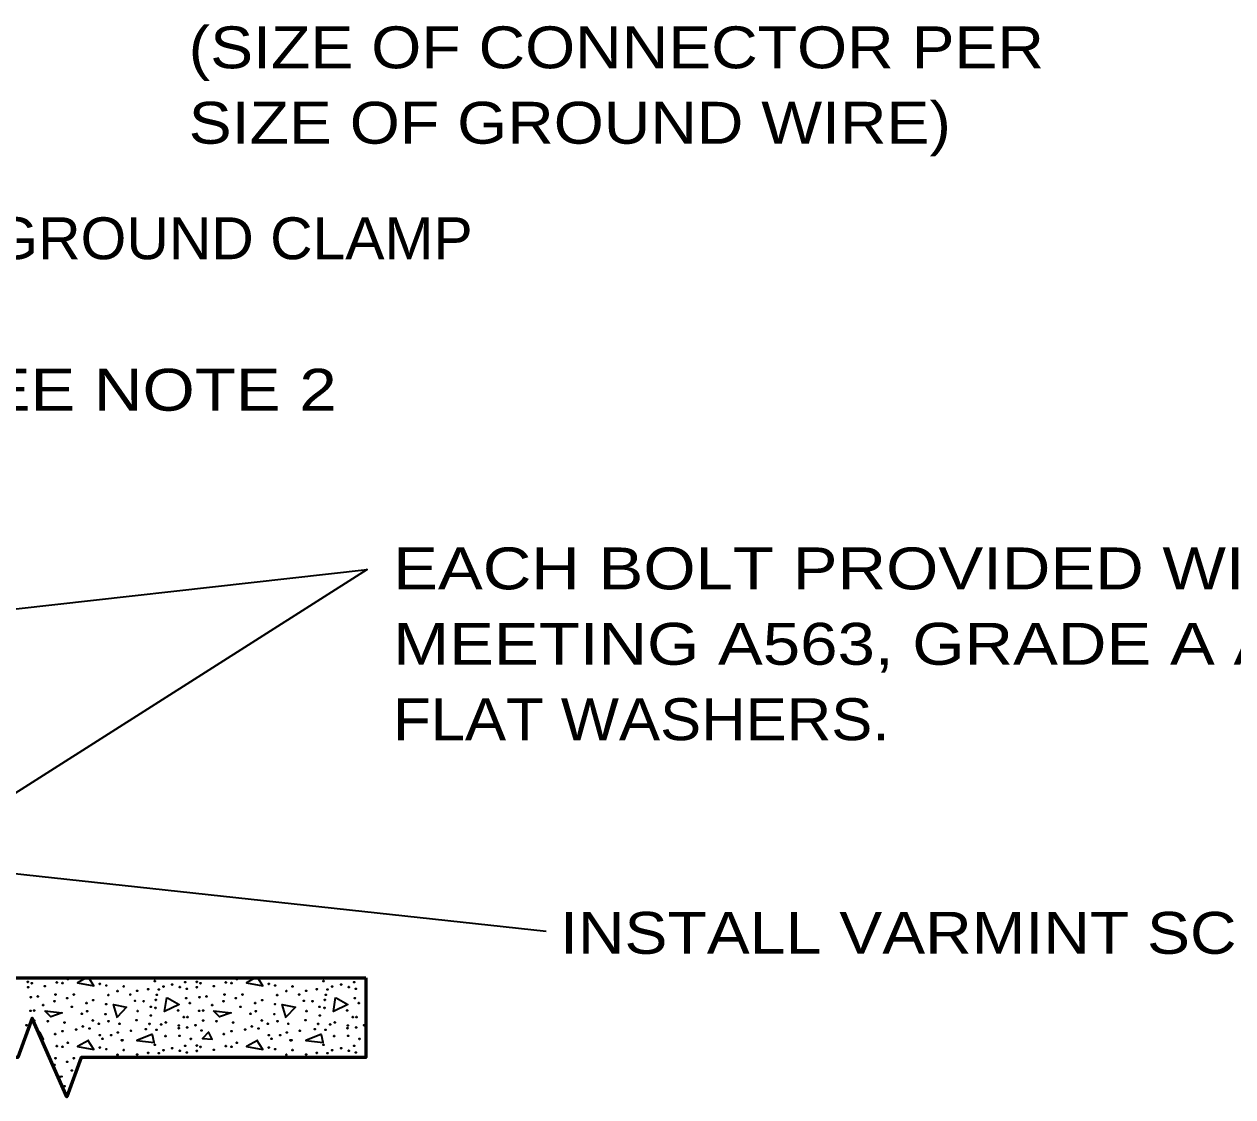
# Model space of a CAD drawing. Extents: x -1 to 679, y 0 to 440.
# Drawn here: x 464.1 to 536.2, y 233.6 to 297.7 of the extents above; entities that cross this region are included whole.
import ezdxf
from ezdxf.enums import TextEntityAlignment as Align

# ---------------------------------------------------------------- set-up
doc = ezdxf.new("R2010")
doc.units = 0
doc.layers.add('1', color=7, linetype='Continuous', lineweight=35)

msp = doc.modelspace()

# ---------------------------------------------------------------- linework, layer by layer
at = {"layer": '1'}
for p, q in [((460.988, 247.244), (495.251, 243.524)), ((465.041, 237.532), (464.96, 237.447))]:
    msp.add_line(p, q, dxfattribs=at)
at = {"layer": '1', "lineweight": 53}
msp.add_line((460.988, 240.744), (484.488, 240.744), dxfattribs=at)
at = {"layer": '1'}
for points in [[(458.988, 262.245), (484.563, 265.111), (458.988, 248.869)], [(467.818, 240.744), (467.281, 240.452), (468.261, 240.272), (467.957, 240.744)], [(471.405, 240.744), (471.861, 240.692), (471.85, 240.744)], [(477.898, 240.744), (477.361, 240.452), (478.341, 240.272), (478.037, 240.744)], [(481.485, 240.744), (481.941, 240.692), (481.93, 240.744)], [(472.641, 239.552), (473.341, 239.152), (472.481, 238.732), (472.601, 239.572)], [(482.721, 239.552), (483.421, 239.152), (482.561, 238.732), (482.681, 239.572)], [(469.661, 238.352), (469.421, 239.152), (470.201, 238.992), (469.641, 238.392)], [(479.741, 238.352), (479.501, 239.152), (480.281, 238.992), (479.721, 238.392)], [(465.113, 237.101), (465.241, 237.092), (465.041, 237.492)], [(471.761, 237.392), (470.821, 237.012), (471.861, 236.892), (471.761, 237.352)], [(475.121, 237.532), (474.741, 237.132), (475.321, 237.092), (475.121, 237.492)], [(481.841, 237.392), (480.901, 237.012), (481.941, 236.892), (481.841, 237.352)], [(467.941, 237.012), (467.281, 236.652), (468.261, 236.472), (467.901, 237.032)], [(478.021, 237.012), (477.361, 236.652), (478.341, 236.472), (477.981, 237.032)], [(466.089, 234.883), (466.361, 234.852), (466.137, 234.773)]]:
    msp.add_lwpolyline(points, dxfattribs=at)
at = {"layer": '1', "lineweight": 53}
msp.add_lwpolyline([(484.488, 240.744), (484.488, 235.994), (467.488, 235.994), (466.633, 233.645), (464.565, 238.344), (463.71, 235.994), (430.238, 235.994), (426.738, 235.994), (381.267, 235.994), (380.412, 233.645), (378.344, 238.344), (377.488, 235.994), (360.488, 235.994)], dxfattribs=at)
at = {"layer": '1'}
for points in [[(465.321, 238.772), (466.361, 238.652), (465.681, 238.412)], [(475.401, 238.772), (476.441, 238.652), (475.761, 238.412)]]:
    msp.add_lwpolyline(points, close=True, dxfattribs=at)
for centre in [(464.314, 240.501), (464.547, 240.421), (465.329, 240.249), (466.045, 240.474), (466.389, 240.435), (466.707, 240.673), (468.616, 240.382), (469, 240.289), (470.034, 240.236), (471.889, 240.554), (472.406, 240.222), (472.936, 240.342), (473.705, 240.488), (474.394, 240.501), (474.627, 240.421), (475.409, 240.249), (476.125, 240.474), (476.469, 240.435), (476.787, 240.673), (478.696, 240.382), (479.08, 240.289), (480.114, 240.236), (481.969, 240.554), (482.486, 240.222), (483.016, 240.342), (483.785, 240.488), (464.327, 240.183), (464.486, 239.586), (464.905, 239.639), (465.965, 239.745), (466.654, 239.533), (467.052, 239.745), (469.119, 239.719), (469.663, 239.957), (470.431, 239.745), (470.842, 239.971), (471.492, 240.063), (472.022, 239.732), (472.128, 240.05), (473.387, 240.196), (473.758, 239.533), (473.811, 240.09), (474.407, 240.183), (474.566, 239.586), (474.985, 239.639), (476.045, 239.745), (476.734, 239.533), (477.132, 239.745), (479.199, 239.719), (479.743, 239.957), (480.511, 239.745), (480.922, 239.971), (481.572, 240.063), (482.102, 239.732), (482.208, 240.05), (483.467, 240.196), (483.838, 239.533), (483.891, 240.09), (464.467, 238.775), (464.693, 238.791), (465.236, 239.122), (465.912, 239.347), (466.933, 239.016), (467.807, 239.241), (468.218, 239.414), (468.987, 239.175), (470.71, 239.374), (470.869, 238.764), (471.227, 239.347), (471.651, 239.016), (471.942, 238.95), (471.956, 239.427), (473.294, 238.804), (473.983, 239.241), (474.547, 238.775), (474.773, 238.791), (475.316, 239.122), (475.992, 239.347), (477.013, 239.016), (477.887, 239.241), (478.298, 239.414), (479.067, 239.175), (480.79, 239.374), (480.949, 238.764), (481.307, 239.347), (481.731, 239.016), (482.022, 238.95), (482.036, 239.427), (483.374, 238.804), (484.063, 239.241), (464.693, 238.194), (465.501, 238.154), (466.495, 238.075), (467.529, 238.605), (467.847, 238.751), (468.192, 238.207), (468.947, 238.579), (469.133, 238.154), (470.803, 238.221), (471.664, 238.499), (472.552, 238.088), (473.625, 238.406), (473.851, 238.406), (474.773, 238.194), (475.581, 238.154), (476.575, 238.075), (477.609, 238.605), (477.927, 238.751), (478.272, 238.207), (479.027, 238.579), (479.213, 238.154), (480.883, 238.221), (481.744, 238.499), (482.632, 238.088), (483.705, 238.406), (483.931, 238.406), (464.235, 237.916), (465.939, 237.39), (466.389, 237.563), (467.198, 237.655), (467.595, 237.849), (467.993, 237.722), (468.55, 238.008), (468.616, 237.324), (469.292, 237.324), (469.689, 237.483), (469.782, 238.008), (470.471, 237.589), (471.359, 237.682), (471.571, 237.995), (471.995, 237.642), (472.274, 237.969), (473.321, 237.735), (473.334, 237.902), (473.824, 237.788), (474.315, 237.916), (474.68, 237.602), (476.019, 237.39), (476.469, 237.563), (477.278, 237.655), (477.675, 237.849), (478.073, 237.722), (478.63, 238.008), (478.696, 237.324), (479.372, 237.324), (479.769, 237.483), (479.862, 238.008), (480.551, 237.589), (481.439, 237.682), (481.651, 237.995), (482.075, 237.642), (482.354, 237.969), (483.401, 237.735), (483.414, 237.902), (483.904, 237.788), (484.395, 237.916), (466.045, 236.674), (466.389, 236.635), (466.707, 236.873), (468.775, 237.112), (469.915, 237.019), (469.968, 237.019), (471.889, 236.754), (472.525, 237.271), (473.36, 237.284), (473.705, 236.688), (474.036, 237.099), (474.394, 236.701), (474.627, 236.621), (476.125, 236.674), (476.469, 236.635), (476.787, 236.873), (478.855, 237.112), (479.995, 237.019), (480.048, 237.019), (481.969, 236.754), (482.605, 237.271), (483.44, 237.284), (483.785, 236.688), (484.116, 237.099), (465.965, 235.945), (467.052, 235.945), (468.616, 236.582), (469, 236.489), (469.663, 236.157), (470.034, 236.436), (470.842, 236.171), (471.492, 236.263), (472.128, 236.25), (472.406, 236.422), (472.936, 236.542), (473.387, 236.396), (473.811, 236.29), (474.407, 236.383), (475.409, 236.449), (478.696, 236.582), (479.08, 236.489), (479.743, 236.157), (480.114, 236.436), (480.922, 236.171), (481.572, 236.263), (482.208, 236.25), (482.486, 236.422), (483.016, 236.542), (483.467, 236.396), (483.891, 236.29), (465.912, 235.547), (466.654, 235.733), (466.933, 235.216), (466.495, 234.275)]:
    msp.add_circle(centre, 0.0265, dxfattribs=at)
for centre, start, end in [((484.474, 240.501), 57.21077, 302.78922), ((484.487, 240.183), 87.52764, 272.47236), ((484.474, 236.701), 57.21077, 302.78922), ((484.487, 236.383), 87.52764, 272.47236)]:
    msp.add_arc(centre, 0.0265, start, end, dxfattribs=at)

# ---------------------------------------------------------------- texts
for s, width, p in [('(SIZE OF CONNECTOR PER', 1.15, (473.916, 295.027)), ('SIZE OF GROUND WIRE)', 1.15, (473.916, 290.527)), ('EACH BOLT PROVIDED WITH TWO HEX NUTS', 1.2, (486.114, 263.93)), ('MEETING A563, GRADE A AND TWO F436', 1.2, (486.114, 259.43)), ('FLAT WASHERS.', 1.1, (486.114, 254.93))]:
    msp.add_text(s, height=2.5, dxfattribs=dict(at, width=width)).set_placement(p)
for s, width, p in [('GROUND CLAMP', 1.05, (476.534, 283.632)), ('SEE NOTE 2', 1.2, (470.935, 274.593)), ('INSTALL VARMINT SCREEN', 1.15, (521.609, 242.181))]:
    msp.add_text(s, height=2.5, dxfattribs=dict(at, width=width)).set_placement(p, align=Align.CENTER)

doc.saveas('drawing.dxf')
